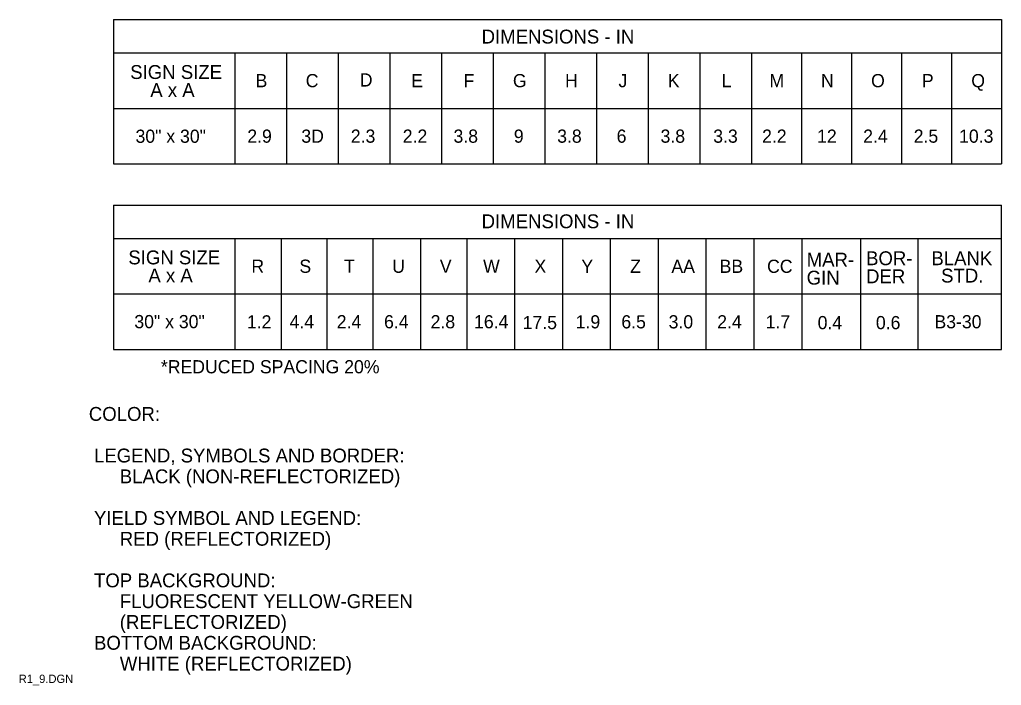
# Model space of a CAD drawing. Extents: x 0.013 to 0.195, y 0.003 to 0.259.
# Drawn here: x 0.0127 to 0.1894, y 0.0028 to 0.1228 of the extents above; entities that cross this region are included whole.
import ezdxf

# ---------------------------------------------------------------- set-up
doc = ezdxf.new("R2010")
doc.units = 0
doc.layers.add('1', color=7, linetype='Continuous')
doc.layers.add('3', color=7, linetype='Continuous')

msp = doc.modelspace()

# ---------------------------------------------------------------- linework, layer by layer
at = {"layer": '3'}
for p, q in [((0.029545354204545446, 0.12276893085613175), (0.029545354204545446, 0.09676893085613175)), ((0.029545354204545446, 0.12276564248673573), (0.1894203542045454, 0.12276564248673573)), ((0.1894203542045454, 0.12276893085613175), (0.1894203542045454, 0.09676893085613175)), ((0.029545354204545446, 0.11676564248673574), (0.1894203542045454, 0.11676564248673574)), ((0.051420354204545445, 0.11676564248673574), (0.051420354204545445, 0.09676893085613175)), ((0.06072035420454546, 0.11676564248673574), (0.06072035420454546, 0.09676893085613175)), ((0.07002035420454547, 0.11676564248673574), (0.07002035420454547, 0.09676893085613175)), ((0.07932035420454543, 0.11676564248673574), (0.07932035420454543, 0.09676893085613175)), ((0.08862035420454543, 0.11676564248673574), (0.08862035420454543, 0.09676893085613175)), ((0.09792035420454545, 0.11676564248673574), (0.09792035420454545, 0.09676893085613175)), ((0.10722035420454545, 0.11676564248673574), (0.10722035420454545, 0.09676893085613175)), ((0.11652035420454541, 0.11676564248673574), (0.11652035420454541, 0.09676893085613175)), ((0.12582035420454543, 0.11676564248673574), (0.12582035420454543, 0.09676893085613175)), ((0.13512035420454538, 0.11676564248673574), (0.13512035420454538, 0.09676893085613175)), ((0.14442035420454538, 0.11676564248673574), (0.14442035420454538, 0.09676893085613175)), ((0.1534203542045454, 0.11676564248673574), (0.1534203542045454, 0.09676893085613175)), ((0.1624203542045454, 0.11676564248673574), (0.1624203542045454, 0.09676893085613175)), ((0.1714203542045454, 0.11676564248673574), (0.1714203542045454, 0.09676893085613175)), ((0.18042035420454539, 0.11676564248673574), (0.18042035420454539, 0.09676893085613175)), ((0.029545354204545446, 0.10676893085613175), (0.1894203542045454, 0.10676893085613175)), ((0.029545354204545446, 0.09676893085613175), (0.1894203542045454, 0.09676893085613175)), ((0.029545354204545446, 0.08931808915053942), (0.029545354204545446, 0.06332137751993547)), ((0.029545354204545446, 0.08931808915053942), (0.1894203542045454, 0.08931808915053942)), ((0.1894203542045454, 0.06332137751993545), (0.1894203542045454, 0.08931808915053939)), ((0.029545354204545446, 0.08331808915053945), (0.1894203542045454, 0.08331808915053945)), ((0.051420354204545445, 0.08331808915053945), (0.051420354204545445, 0.06332137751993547)), ((0.05972318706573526, 0.08331808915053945), (0.05972318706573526, 0.06332137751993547)), ((0.06795264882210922, 0.08331808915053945), (0.06795264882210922, 0.06332137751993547)), ((0.07627276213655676, 0.08331808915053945), (0.07627276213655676, 0.06332137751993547)), ((0.0848648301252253, 0.08331808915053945), (0.0848648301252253, 0.06332137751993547)), ((0.09318494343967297, 0.08331808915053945), (0.09318494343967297, 0.06332137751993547)), ((0.10177417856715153, 0.08331808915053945), (0.10177417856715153, 0.06332137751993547)), ((0.1103906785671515, 0.08331808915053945), (0.1103906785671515, 0.06332137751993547)), ((0.11900717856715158, 0.08331808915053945), (0.11900717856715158, 0.06332137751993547)), ((0.12762367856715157, 0.08331808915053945), (0.12762367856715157, 0.06332137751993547)), ((0.13624017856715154, 0.08331808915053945), (0.13624017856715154, 0.06332137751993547)), ((0.1448566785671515, 0.08331808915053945), (0.1448566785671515, 0.06332137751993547)), ((0.1534731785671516, 0.08331808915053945), (0.1534731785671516, 0.06332137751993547)), ((0.1640348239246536, 0.08331808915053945), (0.1640348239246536, 0.0633213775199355)), ((0.1743873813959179, 0.08331808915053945), (0.1743873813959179, 0.0633213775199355)), ((0.029545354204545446, 0.07332137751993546), (0.1894203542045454, 0.07332137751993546)), ((0.029545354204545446, 0.06332137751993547), (0.1894203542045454, 0.06332137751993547))]:
    msp.add_line(p, q, dxfattribs=at)

# ---------------------------------------------------------------- texts
at = {"layer": '1'}
for s, height, p in [('COLOR:', 0.0024997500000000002, (0.025125, 0.05045599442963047)), (' LEGEND, SYMBOLS AND BORDER:', 0.0024997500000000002, (0.025125, 0.04295649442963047)), ('      BLACK (NON-REFLECTORIZED)', 0.0024997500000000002, (0.025125, 0.039206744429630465)), (' YIELD SYMBOL AND LEGEND:', 0.0024997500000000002, (0.025125, 0.03170724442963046)), ('      RED (REFLECTORIZED)', 0.0024997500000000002, (0.025125, 0.027957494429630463)), (' TOP BACKGROUND:', 0.0024997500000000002, (0.025125, 0.020457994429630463)), ('      FLUORESCENT YELLOW-GREEN', 0.0024997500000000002, (0.025125, 0.016708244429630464)), ('      (REFLECTORIZED)', 0.0024997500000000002, (0.025125, 0.012958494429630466)), (' BOTTOM BACKGROUND:', 0.0024997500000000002, (0.025125, 0.009208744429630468)), ('      WHITE (REFLECTORIZED)', 0.0024997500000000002, (0.025125, 0.005458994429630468)), ('R1_9.DGN', 0.0015, (0.0125, 0.003218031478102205))]:
    msp.add_text(s, height=height, dxfattribs=at).set_placement(p)
at = {"layer": '3'}
for s, height, p in [('DIMENSIONS - IN', 0.0024997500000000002, (0.09584596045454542, 0.11845977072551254)), ('SIGN SIZE', 0.0024997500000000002, (0.032573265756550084, 0.11206969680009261)), ('B', 0.0023752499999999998, (0.055148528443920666, 0.11058477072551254)), ('C', 0.0023752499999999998, (0.0641715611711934, 0.11058477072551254)), ('D', 0.0023752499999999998, (0.07390856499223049, 0.11070977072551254)), ('E', 0.0023752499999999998, (0.0831571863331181, 0.11058477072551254)), ('F', 0.0023752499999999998, (0.09257070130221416, 0.11058477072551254)), ('G', 0.0023752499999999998, (0.1014779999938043, 0.11058477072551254)), ('H', 0.0023752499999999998, (0.11086595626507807, 0.11058477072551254)), ('J', 0.0023752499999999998, (0.12048440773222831, 0.11058477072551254)), ('K', 0.0023752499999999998, (0.12935592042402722, 0.11058477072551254)), ('L', 0.0023752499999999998, (0.13905922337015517, 0.11058477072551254)), ('M', 0.0023752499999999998, (0.14765937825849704, 0.11058477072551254)), ('N', 0.0023752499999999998, (0.15693961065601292, 0.11058477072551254)), ('O', 0.0023752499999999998, (0.16596270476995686, 0.11058477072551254)), ('P', 0.0023752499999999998, (0.17510573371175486, 0.11058477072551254)), ('Q', 0.0023752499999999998, (0.18400144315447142, 0.11058477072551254)), ('A x A', 0.0024997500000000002, (0.03618502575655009, 0.10881994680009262)), ('30" x 30"', 0.0023752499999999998, (0.033532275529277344, 0.10056623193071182)), ('2.9', 0.0023752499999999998, (0.05365708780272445, 0.10058130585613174)), ('3D', 0.0023752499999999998, (0.06338366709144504, 0.10058130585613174)), ('2.3', 0.0023752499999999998, (0.07229183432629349, 0.10058130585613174)), ('2.2', 0.0023752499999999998, (0.08164169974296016, 0.10058130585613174)), ('3.8', 0.0023752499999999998, (0.09078044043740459, 0.10058130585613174)), ('9', 0.0023752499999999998, (0.10164516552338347, 0.10058130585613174)), ('3.8', 0.0023752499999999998, (0.10944655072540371, 0.10058130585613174)), ('6', 0.0023752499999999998, (0.12015084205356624, 0.10058130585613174)), ('3.8', 0.0023752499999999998, (0.1280575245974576, 0.10058130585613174)), ('3.3', 0.0023752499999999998, (0.13754204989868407, 0.10058130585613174)), ('2.2', 0.0023752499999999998, (0.14634046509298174, 0.10058130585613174)), ('12', 0.0023752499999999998, (0.15624574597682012, 0.10058130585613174)), ('2.4', 0.0023752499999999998, (0.16453746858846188, 0.10058130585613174)), ('2.5', 0.0023752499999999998, (0.1736370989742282, 0.10058130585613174)), ('10.3', 0.0023752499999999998, (0.18180811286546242, 0.10058130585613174)), ('DIMENSIONS - IN', 0.0024997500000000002, (0.09584596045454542, 0.08517290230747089)), ('SIGN SIZE', 0.0024997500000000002, (0.03223579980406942, 0.07866227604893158)), ('S', 0.0023752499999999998, (0.06303719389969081, 0.07713721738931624)), ('MAR-', 0.0024997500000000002, (0.1543670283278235, 0.07826221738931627)), ('BOR-', 0.0024997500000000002, (0.16506202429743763, 0.07851221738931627)), ('BLANK', 0.0024997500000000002, (0.17682254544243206, 0.07851221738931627)), ('A x A', 0.0024997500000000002, (0.03584755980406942, 0.07541252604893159)), ('R', 0.0023752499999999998, (0.05439148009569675, 0.07713721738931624)), ('T', 0.0023752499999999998, (0.07106280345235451, 0.07713721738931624)), ('U', 0.0023752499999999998, (0.0797382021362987, 0.07713721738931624)), ('V', 0.0023752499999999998, (0.08831857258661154, 0.07713721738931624)), ('W', 0.0023752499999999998, (0.09610971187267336, 0.07713721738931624)), ('X', 0.0023752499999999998, (0.10536407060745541, 0.07713721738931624)), ('Y', 0.0023752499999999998, (0.11380277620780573, 0.07712607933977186)), ('Z', 0.0023752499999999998, (0.12256779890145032, 0.07712607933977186)), ('AA', 0.0023752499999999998, (0.13001408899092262, 0.07712607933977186)), ('BB', 0.0023752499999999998, (0.13869464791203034, 0.07712607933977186)), ('CC', 0.0023752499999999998, (0.14724113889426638, 0.07712607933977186)), ('STD.', 0.0024997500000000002, (0.17857254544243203, 0.07538721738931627)), ('GIN', 0.0024997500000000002, (0.1543670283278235, 0.07501221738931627)), ('DER', 0.0024997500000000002, (0.16506202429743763, 0.07526221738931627)), ('30" x 30"', 0.0023752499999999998, (0.03331980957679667, 0.06715881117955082)), ('1.2', 0.0023752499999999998, (0.05357631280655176, 0.06710997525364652)), ('4.4', 0.0023752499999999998, (0.06126303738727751, 0.06713375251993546)), ('2.4', 0.0023752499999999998, (0.06975932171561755, 0.06713375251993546)), ('6.4', 0.0023752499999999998, (0.07827656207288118, 0.06713375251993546)), ('2.8', 0.0023752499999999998, (0.08665780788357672, 0.06713375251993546)), ('16.4', 0.0023752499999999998, (0.09448131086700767, 0.06713375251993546)), ('17.5', 0.0023752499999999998, (0.1032303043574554, 0.06698424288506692)), ('1.9', 0.0023752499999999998, (0.11277817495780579, 0.06712261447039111)), ('6.5', 0.0023752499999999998, (0.12100438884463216, 0.06712261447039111)), ('3.0', 0.0023752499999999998, (0.12951072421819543, 0.06712261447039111)), ('2.4', 0.0023752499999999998, (0.1382603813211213, 0.06712261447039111)), ('1.7', 0.0023752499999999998, (0.14698933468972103, 0.06712261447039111)), ('0.4', 0.0023752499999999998, (0.15634291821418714, 0.0669762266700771)), ('0.6', 0.0023752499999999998, (0.16682975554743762, 0.0669762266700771)), ('B3-30', 0.0023752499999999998, (0.17736766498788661, 0.06713375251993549)), ('*REDUCED SPACING 20%', 0.0023752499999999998, (0.03809911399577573, 0.05902225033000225))]:
    msp.add_text(s, height=height, dxfattribs=at).set_placement(p)

doc.saveas('drawing.dxf')
